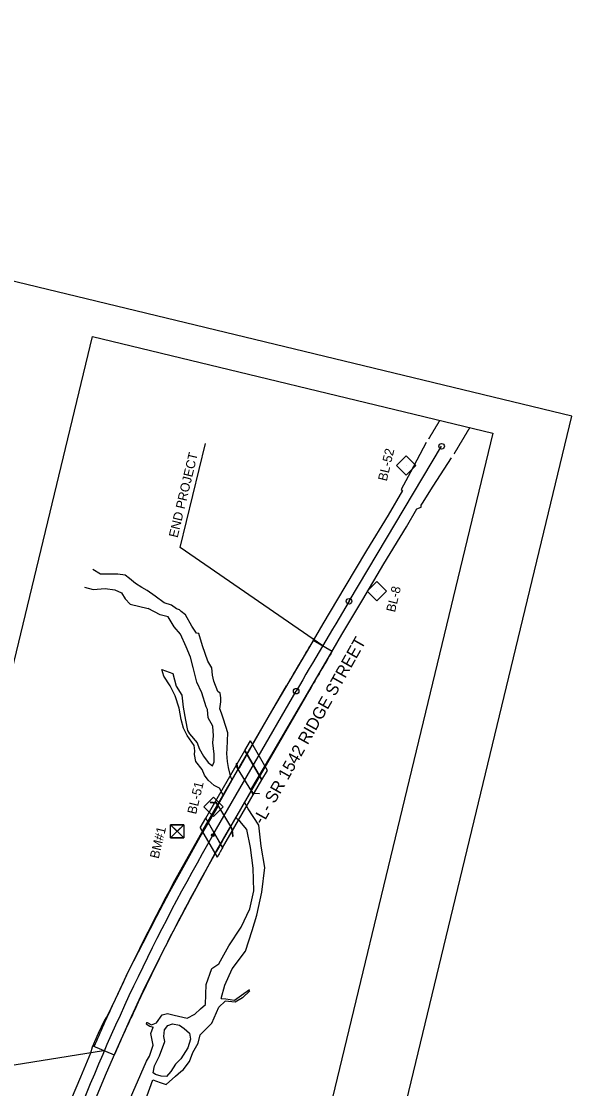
# Model space of a CAD drawing. Extents: x 1649669 to 1659218, y 588594 to 607900.
# Drawn here: x 1656826 to 1659218, y 603109 to 607744 of the extents above; entities that cross this region are included whole.
import ezdxf

# ---------------------------------------------------------------- set-up
doc = ezdxf.new("R2010")
doc.units = 0
for name, color, linetype in [('CTL Bench Mark CELL', 7, 'Continuous'), ('CTL Bench Mark Text', 7, 'Continuous'), ('CTL Sheet Border CELL', 7, 'Continuous'), ('CTL Sheet Notes CELL', 7, 'Continuous'), ('CTL Supplemental Horizontal and Vertical CELL', 7, 'Continuous'), ('CTL Supplemental Horizontal and Vertical Text', 7, 'Continuous'), ('Default', 7, 'Continuous'), ('Exist Hydro Jurisdictional Stream or Body of Water', 7, 'Continuous'), ('Exist Hydro Stream or Body of Water', 7, 'Continuous'), ('Exist Roads EOP', 7, 'Continuous'), ('Exist Structure Major Bridge WW', 7, 'Continuous'), ('Exist Structure Major Deck Tunnel Box Culvert', 7, 'Continuous'), ('Old_Level_3', 7, 'Continuous'), ('Prop EOT', 7, 'Continuous'), ('Prop Horizontal Alignment', 7, 'Continuous'), ('Prop Horizontal Alignment Station Label', 7, 'Continuous'), ('Sheet Data Field CELL', 7, 'Continuous')]:
    doc.layers.add(name, color=color, linetype=linetype)

msp = doc.modelspace()

# ---------------------------------------------------------------- linework, layer by layer
at = {"layer": 'CTL Bench Mark CELL'}
msp.add_line((1657504, 604226.4), (1657504, 604226.4), dxfattribs=at)
msp.add_lwpolyline([(1657475.2, 604255.1), (1657532.7, 604255.1), (1657532.7, 604197.6), (1657475.2, 604197.6)], close=True, dxfattribs=at)
for points in [[(1657532.7, 604255.1), (1657475.2, 604197.6), (1657503.9, 604226.4), (1657532.7, 604197.6), (1657475.2, 604255.1)], [(1657503.9, 604226.4), (1657532.7, 604255.1), (1657475.2, 604255.1), (1657503.9, 604226.4)], [(1657503.9, 604226.4), (1657475.2, 604197.6), (1657532.7, 604197.6), (1657503.9, 604226.4)]]:
    msp.add_lwpolyline(points, dxfattribs=at)
at = {"layer": 'CTL Sheet Border CELL'}
msp.add_lwpolyline([(1652117.6, 607744.3), (1649668.6, 597600.9), (1656768.8, 595886.6), (1659217.9, 606030)], close=True, dxfattribs=at)
at = {"layer": 'CTL Sheet Notes CELL'}
msp.add_lwpolyline([(1656065.2, 601942.6), (1657135.7, 606376.1), (1658875.8, 605955.9), (1657805.4, 601522.5)], close=True, dxfattribs=at)
at = {"layer": 'CTL Supplemental Horizontal and Vertical CELL'}
for p, q in [((1658498.4, 605814.6), (1658498.4, 605814.6)), ((1658371.4, 605268.9), (1658371.4, 605268.9)), ((1657660.8, 604332.4), (1657660.8, 604332.4))]:
    msp.add_line(p, q, dxfattribs=at)
for points in [[(1658456.7, 605814.7), (1658498.6, 605856.7), (1658540.6, 605814.7), (1658498.7, 605772.7)], [(1658329.7, 605269), (1658371.6, 605310.9), (1658413.6, 605268.9), (1658371.7, 605227)], [(1657619.1, 604332.5), (1657661, 604374.5), (1657703, 604332.5), (1657661.1, 604290.5)]]:
    msp.add_lwpolyline(points, close=True, dxfattribs=at)
at = {"layer": 'Default'}
for p, q in [((1657517.1, 605459.4), (1657626, 605910.7)), ((1658136.1, 605032.3), (1657517.1, 605459.4)), ((1657871.5, 604449.5), (1657797.7, 604577.6)), ((1657701, 604155.5), (1657627.4, 604283.3)), ((1656526.1, 603168.4), (1657183.3, 603275.1))]:
    msp.add_line(p, q, dxfattribs=at)
at = {"layer": 'Exist Hydro Jurisdictional Stream or Body of Water'}
for points in [[(1657407.7, 605248.2), (1657373.9, 605271.9), (1657350.4, 605285.8), (1657322.1, 605303), (1657296.6, 605324.1), (1657277.4, 605338.5), (1657245.2, 605343.9), (1657200, 605343.9), (1657170.1, 605343.1), (1657137.2, 605363)], [(1657101.1, 605286.4), (1657138.9, 605276.3), (1657190.3, 605281.5), (1657233.1, 605275), (1657262.2, 605261.6), (1657277.2, 605236.2), (1657298.7, 605212.8), (1657377.8, 605194.3)], [(1657689.7, 604826.3), (1657680.6, 604834.1), (1657663.5, 604878.4), (1657657.4, 604905), (1657654, 604936.5), (1657636.6, 604964.7), (1657613.4, 605031.9), (1657598.2, 605085.1), (1657587.6, 605087.5), (1657567.5, 605117.4), (1657539.2, 605166.1), (1657521.1, 605181.4), (1657513, 605188.8), (1657501, 605193), (1657478.4, 605208.6), (1657446.4, 605218.5), (1657407.7, 605248.2)], [(1657629.4, 604767.3), (1657610.2, 604828), (1657589.1, 604874), (1657573.7, 604937.8), (1657561, 604982.5), (1657542.5, 605027.3), (1657517.4, 605083.3), (1657489.8, 605114.4), (1657464.7, 605157.8), (1657430.2, 605166.8), (1657377.8, 605194.3)], [(1657591.1, 604611.2), (1657598.6, 604585.8), (1657617.5, 604553.5), (1657638, 604525.2), (1657657.1, 604511.5), (1657663.9, 604528), (1657664.4, 604561.4), (1657658.6, 604610.2), (1657660.8, 604640.8), (1657658.4, 604683.5), (1657638, 604719.8), (1657635.5, 604754.9), (1657629.4, 604767.3)], [(1657742.7, 604450.5), (1657736.8, 604461.4), (1657726.8, 604503.2), (1657722.4, 604530), (1657719, 604565), (1657721.3, 604584.2), (1657724.3, 604654.8), (1657705.5, 604713.7), (1657696.6, 604739.7)], [(1657705, 604383.3), (1657699.7, 604392.7), (1657687.9, 604413.1), (1657664.7, 604424.8), (1657637.7, 604449.1), (1657622.9, 604469.9), (1657612, 604495), (1657585, 604528.9), (1657578.6, 604560), (1657579.6, 604576.1), (1657576.9, 604598.6)], [(1657694.4, 603500.4), (1657710.2, 603558), (1657743, 603629), (1657799.8, 603705.5), (1657829.3, 603795.6), (1657849.2, 603862.1), (1657871.6, 603961.8), (1657885.2, 604069.1), (1657869, 604162), (1657858.3, 604253.5), (1657812.5, 604324), (1657796.5, 604352.9)], [(1657547.6, 603414.2), (1657580.3, 603432.7), (1657605, 603454.7), (1657627, 603473.6), (1657629.2, 603561.5), (1657654.1, 603630.3), (1657683.9, 603650.7), (1657728.4, 603728.9), (1657782.2, 603810.2), (1657819.2, 603889.2), (1657836.8, 603968.5), (1657833.1, 604066.8), (1657822.9, 604155.9), (1657805.8, 604235), (1657776.5, 604271.1), (1657761.7, 604282.3), (1657758.9, 604287.2)], [(1657603.6, 603342.6), (1657654.4, 603392.6), (1657684, 603462.5)], [(1657413.3, 603394.5), (1657437.7, 603429.3), (1657461.8, 603434.9), (1657490, 603427.5), (1657547.6, 603414.2)], [(1657286, 603035.1), (1657370.9, 603227.8), (1657382.9, 603249.5), (1657399.3, 603296.9), (1657388.8, 603347.6), (1657399, 603375.8)], [(1657370.1, 603395.8), (1657369.3, 603390.9), (1657384.6, 603380), (1657399, 603375.8)], [(1657370.1, 603395.8), (1657373.4, 603396.1), (1657391.7, 603386.6), (1657413.3, 603394.5)], [(1657399.4, 603177.9), (1657404.9, 603207.7), (1657426.5, 603251.4), (1657449.9, 603313.5), (1657446.2, 603334.8), (1657448.7, 603364.7), (1657463.4, 603382.3), (1657483.2, 603390.3), (1657513.5, 603384.8), (1657533.9, 603370.1), (1657557.2, 603349.9)], [(1657507.5, 602538.4), (1657458.2, 602609.5), (1657416.5, 602677.6), (1657384.9, 602750), (1657344.5, 602848.7), (1657343.1, 602919.3), (1657357.3, 603010.2), (1657365.6, 603059.3), (1657397.4, 603146.9)]]:
    msp.add_lwpolyline(points, dxfattribs=at)
at = {"layer": 'Exist Hydro Stream or Body of Water'}
for points in [[(1657436.3, 604928.9), (1657484.9, 604912), (1657499.5, 604857), (1657524.4, 604818.2), (1657529.8, 604765.4), (1657540.2, 604708.9), (1657548.7, 604664.3), (1657557, 604649.3), (1657591.1, 604611.2)], [(1657576.9, 604598.6), (1657547.1, 604642.7), (1657531.6, 604674.3), (1657521, 604712.1), (1657512.8, 604761.1), (1657495.2, 604814.6), (1657472.8, 604858.8), (1657446, 604900.2), (1657436.3, 604928.9)], [(1657696.6, 604739.7), (1657688.6, 604757.7), (1657693.1, 604789), (1657693.7, 604806.5), (1657689.7, 604826.3)], [(1657819.4, 603533.5), (1657787.1, 603502.9), (1657755.6, 603484.1), (1657712.7, 603488.6), (1657684, 603462.5)], [(1657694.4, 603500.4), (1657715.4, 603498.3), (1657752.4, 603493.3), (1657783.8, 603515.3), (1657818.3, 603539.4)], [(1657557.2, 603349.9), (1657561.5, 603323.5), (1657549.8, 603285.4), (1657520.1, 603238.6), (1657496.8, 603214.8), (1657476.1, 603183.7), (1657456.6, 603160.9), (1657433.7, 603163), (1657409.2, 603170.1), (1657399.4, 603177.9)], [(1657529.7, 603190.8), (1657557.2, 603226), (1657571.9, 603265.9), (1657594.9, 603306.8), (1657603.6, 603342.6)], [(1657397.4, 603146.9), (1657429.9, 603135.3), (1657455.1, 603126.3), (1657496.6, 603162.7), (1657520.2, 603183.2), (1657529.7, 603190.8)]]:
    msp.add_lwpolyline(points, dxfattribs=at)
at = {"layer": 'Exist Roads EOP'}
for points in [[(1658585.3, 605915.1), (1658516.8, 605786.1), (1658476.8, 605710.3), (1658482.6, 605707), (1658419.9, 605599.4), (1658326.7, 605446.2), (1658232.3, 605288.5), (1658136.3, 605127.5), (1658078.3, 605027.7), (1658007.6, 604907.9), (1657917.7, 604755.1), (1657829.4, 604600), (1657772.3, 604500.3), (1657768.4, 604495.7)], [(1657824.9, 604402.6), (1657824.8, 604403.9), (1657823.3, 604406), (1657910.1, 604552.6), (1657999.9, 604706.5), (1658090.5, 604860.4), (1658159.9, 604978.5), (1658219.6, 605081.3), (1658310.1, 605232.9), (1658401.9, 605387.7), (1658500.2, 605548.4), (1658545, 605627.2), (1658563.4, 605634.7), (1658564.3, 605643.1), (1658569.4, 605651.7), (1658616.7, 605725.7), (1658696.2, 605848.6)], [(1657680.1, 604338.1), (1657678.8, 604333.2), (1657609.1, 604214), (1657534.8, 604081.5), (1657470.9, 603964.2), (1657413.5, 603855.7), (1657353.7, 603741.1), (1657294, 603623), (1657234.6, 603495.5), (1657198.1, 603420.9), (1657194.5, 603417.8), (1657185.8, 603402.8), (1657159.9, 603348.9), (1657133.9, 603288.6), (1657126.9, 603263.4), (1657083.5, 603158.1), (1657043.3, 603063.5), (1657031.4, 603026.1), (1656968.2, 602861.3), (1656900.7, 602680.1)], [(1656990.4, 602647.8), (1657057.1, 602825.7), (1657113.6, 602973.4), (1657153.3, 603073.9), (1657192, 603166.7), (1657236.3, 603270), (1657296.5, 603403), (1657356, 603531.9), (1657419.3, 603660.9), (1657485.8, 603791), (1657560.9, 603933.1), (1657615, 604032.2), (1657671.8, 604137.5), (1657731.7, 604242.7), (1657735.6, 604246.4)]]:
    msp.add_lwpolyline(points, dxfattribs=at)
for points in [[(1658597.7, 605931.6), (1658598.7, 605933.2), (1658599.6, 605934.7), (1658600.5, 605936.3), (1658601.4, 605937.8), (1658602.4, 605939.4), (1658603.3, 605940.9), (1658604.2, 605942.5), (1658605.1, 605944), (1658606.1, 605945.5), (1658607, 605947.1), (1658607.9, 605948.6), (1658608.8, 605950.2), (1658609.8, 605951.7), (1658610.7, 605953.3), (1658611.6, 605954.8), (1658612.5, 605956.4), (1658613.5, 605957.9), (1658614.4, 605959.5), (1658615.3, 605961), (1658616.2, 605962.6), (1658617.2, 605964.1), (1658618.1, 605965.6), (1658619, 605967.2), (1658619.9, 605968.7), (1658620.8, 605970.3), (1658621.8, 605971.8), (1658622.7, 605973.4), (1658623.6, 605974.9), (1658624.5, 605976.5), (1658625.5, 605978), (1658626.4, 605979.6), (1658627.3, 605981.1), (1658628.2, 605982.7), (1658629.2, 605984.2), (1658630.1, 605985.8), (1658631, 605987.3), (1658631.9, 605988.8), (1658632.9, 605990.4), (1658633.8, 605991.9), (1658634.7, 605993.5), (1658635.6, 605995), (1658636.6, 605996.6), (1658637.5, 605998.1), (1658638.4, 605999.7), (1658639.3, 606001.2), (1658640.2, 606002.8), (1658641.2, 606004.3), (1658642.1, 606005.9), (1658643, 606007.4), (1658643.9, 606008.9), (1658644.9, 606010.5), (1658645.1, 606010.8), (1658645.3, 606011.2), (1658645.5, 606011.5)], [(1658707.6, 605866), (1658708.5, 605867.5), (1658709.5, 605869.1), (1658710.4, 605870.6), (1658711.3, 605872.1), (1658712.2, 605873.7), (1658713.2, 605875.2), (1658714.1, 605876.8), (1658715, 605878.3), (1658715.9, 605879.9), (1658716.9, 605881.4), (1658717.8, 605883), (1658718.7, 605884.5), (1658719.6, 605886.1), (1658720.6, 605887.6), (1658721.5, 605889.2), (1658722.4, 605890.7), (1658723.3, 605892.3), (1658724.3, 605893.8), (1658725.2, 605895.3), (1658726.1, 605896.9), (1658727, 605898.4), (1658727.9, 605900), (1658728.9, 605901.5), (1658729.8, 605903.1), (1658730.7, 605904.6), (1658731.6, 605906.2), (1658732.6, 605907.7), (1658733.5, 605909.3), (1658734.4, 605910.8), (1658735.3, 605912.4), (1658736.3, 605913.9), (1658737.2, 605915.5), (1658738.1, 605917), (1658739, 605918.6), (1658740, 605920.1), (1658740.9, 605921.6), (1658741.8, 605923.2), (1658742.7, 605924.7), (1658743.7, 605926.3), (1658744.6, 605927.8), (1658745.5, 605929.4), (1658746.4, 605930.9), (1658747.4, 605932.5), (1658748.3, 605934), (1658749.2, 605935.6), (1658750.1, 605937.1), (1658751.1, 605938.7), (1658752, 605940.2), (1658752.9, 605941.8), (1658753.8, 605943.3), (1658754.8, 605944.9), (1658755.7, 605946.4), (1658756.6, 605948), (1658757.5, 605949.5), (1658758.5, 605951), (1658759.4, 605952.6), (1658760.3, 605954.1), (1658761.2, 605955.7), (1658762.2, 605957.2), (1658763.1, 605958.8), (1658764, 605960.3), (1658764.9, 605961.9), (1658765.8, 605963.4), (1658766.8, 605965), (1658767.7, 605966.5), (1658768.6, 605968.1), (1658769.5, 605969.6), (1658770.5, 605971.2), (1658771.4, 605972.7), (1658772.3, 605974.3), (1658773.2, 605975.8), (1658774.2, 605977.4), (1658774.7, 605978.3), (1658775.2, 605979.2), (1658775.8, 605980.1)]]:
    msp.add_open_spline(points, degree=3, dxfattribs=at)
at = {"layer": 'Exist Structure Major Bridge WW'}
for points in [[(1657766.8, 604501.9), (1657761.6, 604510.8), (1657759.9, 604510.3), (1657764.9, 604500.7), (1657826.7, 604399.2)], [(1657761.8, 604510.4), (1657761.1, 604521.5), (1657762.7, 604521.7), (1657763.8, 604507.1)], [(1657827.8, 604399.4), (1657835, 604387.4), (1657833.8, 604386.7), (1657826.7, 604399.2)], [(1657832.2, 604392.1), (1657860.6, 604390.8), (1657860.2, 604389.4), (1657833.3, 604390.2)], [(1657672.9, 604350.6), (1657648.2, 604353.3), (1657647.5, 604352), (1657673.7, 604349)], [(1657677.4, 604341.7), (1657671.7, 604352.9), (1657672.3, 604353.2), (1657678.1, 604342.1)], [(1657678.1, 604342.1), (1657739.9, 604239.8), (1657745.8, 604230.3), (1657745.2, 604229.6), (1657739.1, 604238.8)], [(1657741.7, 604234.9), (1657744.1, 604204.1), (1657746.2, 604204.7), (1657743.6, 604232.1)]]:
    msp.add_lwpolyline(points, dxfattribs=at)
at = {"layer": 'Exist Structure Major Deck Tunnel Box Culvert'}
for points in [[(1657767.5, 604494.7), (1657680.5, 604339.8)], [(1657735.6, 604246.4), (1657824.9, 604402.6)]]:
    msp.add_lwpolyline(points, dxfattribs=at)
at = {"layer": 'Old_Level_3'}
for p, q in [((1657797.7, 604577.6), (1657821.7, 604619.1)), ((1657895.5, 604491.1), (1657821.7, 604619.1)), ((1657627.4, 604283.3), (1657797.7, 604577.6)), ((1657797.7, 604577.6), (1657871.5, 604449.5)), ((1657871.5, 604449.5), (1657895.5, 604491.1)), ((1657701.2, 604155.2), (1657871.5, 604449.5)), ((1657603.3, 604241.7), (1657627.4, 604283.3)), ((1657701.3, 604155), (1657627.4, 604283.3)), ((1657603.3, 604241.7), (1657677.2, 604113.5))]:
    msp.add_line(p, q, dxfattribs=at)
msp.add_arc((1665517.8, 599661.9), 9016, 150.10778, 150.41407, dxfattribs=at)
at = {"layer": 'Prop EOT'}
for p, q in [((1658095, 605056.4), (1658177.1, 605008.1)), ((1657617.1, 604233.4), (1657979, 604858.9)), ((1657700.1, 604185.4), (1658062.1, 604810.8)), ((1657136.8, 603295.2), (1657229.8, 603254.9))]:
    msp.add_line(p, q, dxfattribs=at)
for centre, radius, start, end in [((1685662, 588712.5), 32047.8, 149.3372, 149.69477), ((1685721.4, 588814.2), 31952, 149.54773, 149.90637), ((1685718, 588808.3), 32048, 149.89309, 149.9451), ((1685718, 588808.3), 31952, 149.89416, 149.9451), ((1665517.8, 599661.9), 9128, 149.9451, 155.30659), ((1665517.8, 599661.9), 9032, 149.9451, 155.29325), ((1665517.8, 599661.9), 9128, 155.30659, 156.56208), ((1665494.5, 599609.8), 9032.8, 154.93139, 156.20023)]:
    msp.add_arc(centre, radius, start, end, dxfattribs=at)
at = {"layer": 'Prop Horizontal Alignment'}
for p, q in [((1658250.3, 605225.6), (1658652.7, 605898.8)), ((1657658.6, 604209.4), (1658020.5, 604834.9))]:
    msp.add_line(p, q, dxfattribs=at)
for centre, radius, start, end in [((1685718, 588808.3), 32000, 149.13342, 149.9451), ((1665517.8, 599661.9), 9080, 149.9451, 159.30371)]:
    msp.add_arc(centre, radius, start, end, dxfattribs=at)
at = {"layer": 'Prop Horizontal Alignment Station Label'}
for centre, radius in [((1658652.7, 605898.8), 12), ((1658250.3, 605225.6), 12), ((1658020.5, 604834.9), 12), ((1657658.6, 604209.4), 6), ((1657658.6, 604209.4), 6)]:
    msp.add_circle(centre, radius, dxfattribs=at)

# ---------------------------------------------------------------- texts
at = {"layer": 'CTL Bench Mark Text'}
msp.add_text('BM#1', height=40, rotation=76.4261, dxfattribs=at).set_placement((1657422.8, 604105.3))
at = {"layer": 'CTL Supplemental Horizontal and Vertical Text'}
for s, p in [('BL-52', (1658414.2, 605744.9)), ('BL-8', (1658449.9, 605175.5)), ('BL-51', (1657585.6, 604298))]:
    msp.add_text(s, height=40, rotation=76.4261, dxfattribs=at).set_placement(p)
at = {"layer": 'Default'}
msp.add_text('END PROJECT', height=40, rotation=76.4261, dxfattribs=at).set_placement((1657505.3, 605499.2))
at = {"layer": 'Sheet Data Field CELL'}
msp.add_text('-L- SR 1542 RIDGE STREET', height=52.501, rotation=60.5969, dxfattribs=at).set_placement((1657875.3, 604252.2))

doc.saveas('drawing.dxf')
